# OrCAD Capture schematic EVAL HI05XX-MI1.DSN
size A; title: EVAL HI05XX-MI1; rev: A0; note: 1
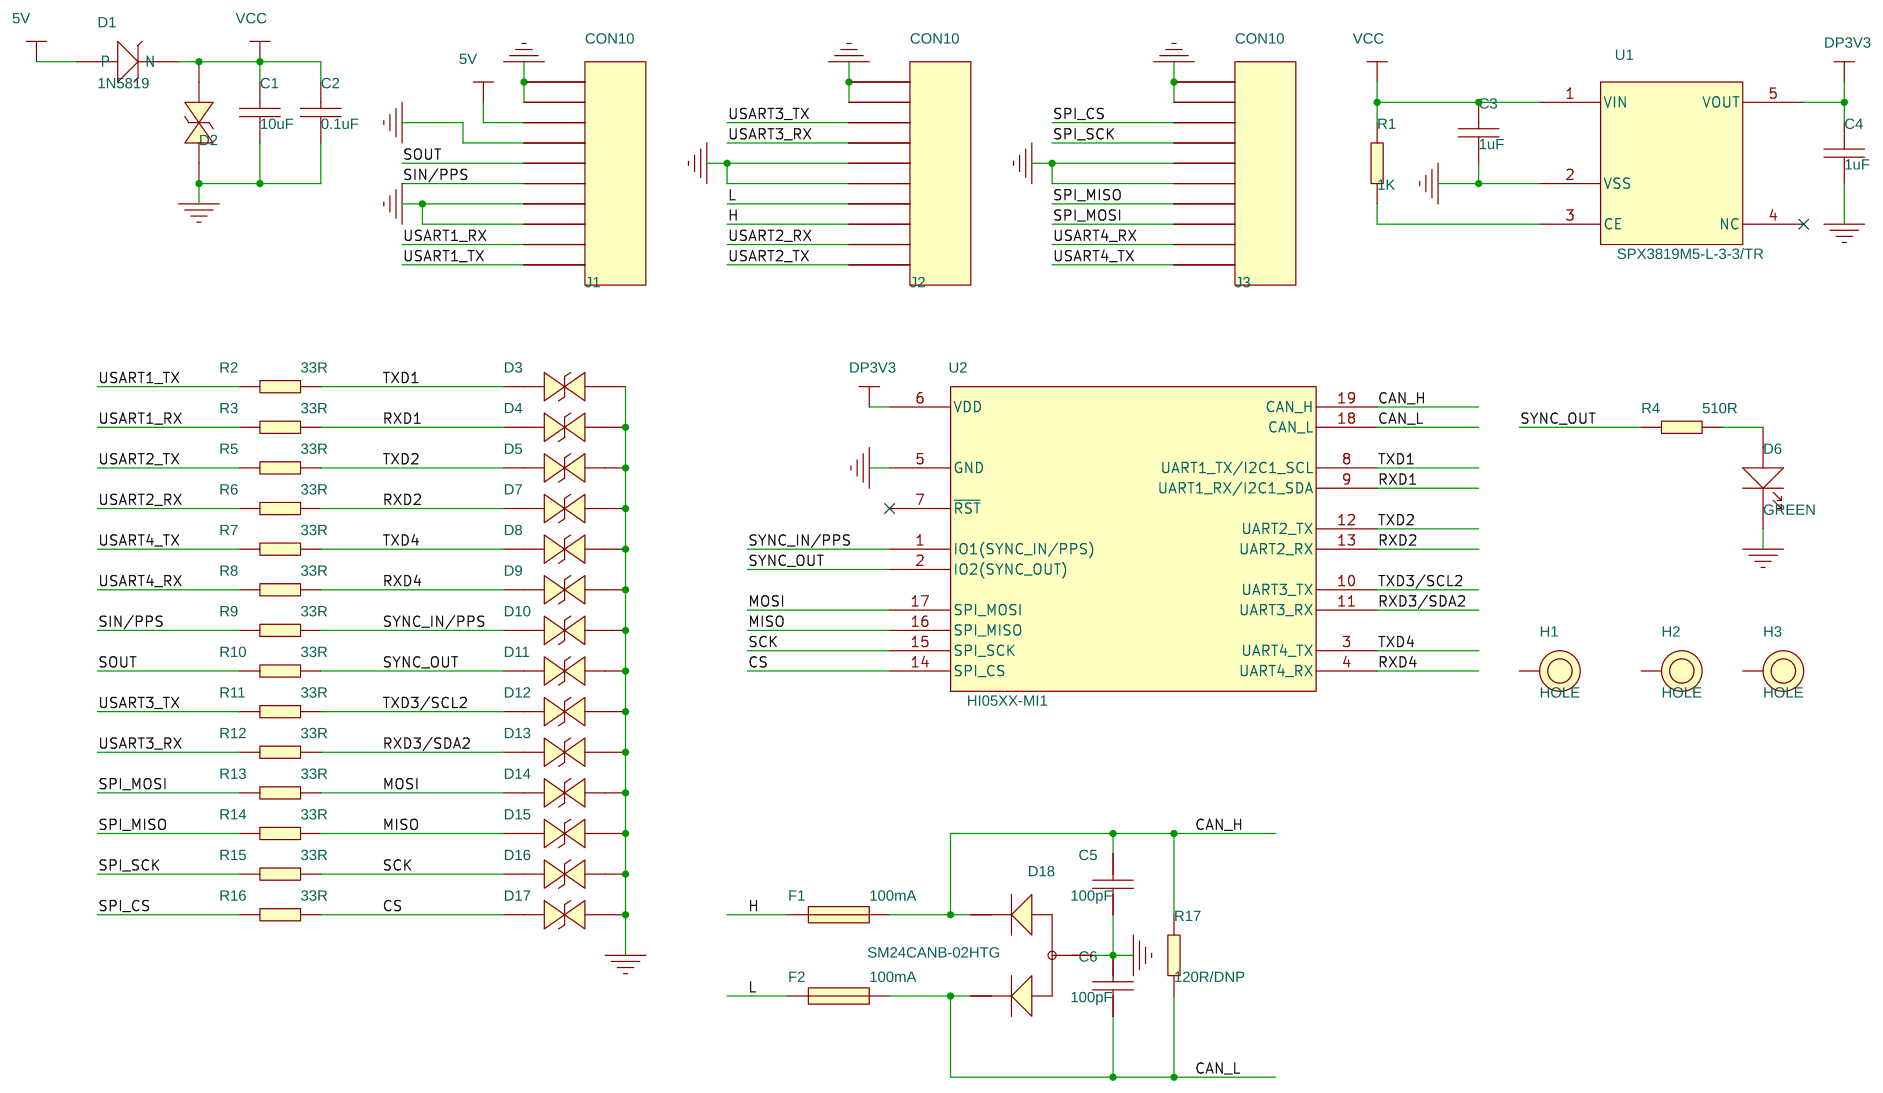
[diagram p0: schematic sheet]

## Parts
C1  10uF  [C0603]
C2  0.1uF  [C0402]
C3  1uF  [C0402]
C4  1uF  [C0402]
C5  100pF  [C0402]
C6  100pF  [C0402]
D1  1N5819  [SOD123FL]
D2  SDD32A05L01  [SOD123FL]
D3  SBD52C05L01  [SOD-523]
D4  SBD52C05L01  [SOD-523]
D5  SBD52C05L01  [SOD-523]
D6  GREEN  [LED0402]
D7  SBD52C05L01  [SOD-523]
D8  SBD52C05L01  [SOD-523]
D9  SBD52C05L01  [SOD-523]
D10  SBD52C05L01  [SOD-523]
D11  SBD52C05L01  [SOD-523]
D12  SBD52C05L01  [SOD-523]
D13  SBD52C05L01  [SOD-523]
D14  SBD52C05L01  [SOD-523]
D15  SBD52C05L01  [SOD-523]
D16  SBD52C05L01  [SOD-523]
D17  SBD52C05L01  [SOD-523]
D18  SM24CANB-02HTG  [SOT23-3-0_95]
F1  100mA  [F0603]
F2  100mA  [F0603]
H1  HOLE  [HOLE-2-MM]
H2  HOLE  [HOLE-2-MM]
H3  HOLE  [HOLE-2-MM]
J1  CON10  [5015680807_1]
J2  CON10  [5015680807_1]
J3  CON10  [5015680807_1]
R1  1K  [R0402]
R2  33R  [R0402]
R3  33R  [R0402]
R4  510R  [R0402]
R5  33R  [R0402]
R6  33R  [R0402]
R7  33R  [R0402]
R8  33R  [R0402]
R9  33R  [R0402]
R10  33R  [R0402]
R11  33R  [R0402]
R12  33R  [R0402]
R13  33R  [R0402]
R14  33R  [R0402]
R15  33R  [R0402]
R16  33R  [R0402]
R17  120R/DNP  [R0805]
U1  SPX3819M5-L-3-3/TR  [SOT23-5-0_95]
U2  HI05XX-MI1  [HI02_HI05]

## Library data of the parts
C1-C6 = Capacity_Nonpolarity
D1 = diode
D2-D5 D7-D17 = DIODE_BI-DIR_TRIG
D6 = LED
D18 = BAT54A_SOT
F1 F2 = Fuse
H1-H3 = HOLE
J1-J3 = CON10
R1-R17 = Res
U1 = XC6210
U2 = HI05XX-MI1

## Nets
5V: D1.1(P) J1.8
GND: C1.1 C2.1 C3.2 C4.1 C5.2 C6.1 D2.1 D3.1 D4.1 D5.1 D6.2(-) D7.1 D8.1 D9.1 D10.1 D11.1 D12.1 D13.1 D14.1 D15.1 D16.1 D17.1 D18.3 J1.3 J1.4 J1.7 J1.9 J1.10 J2.5 J2.6 J2.9 J2.10 J3.5 J3.6 J3.9 J3.10 U1.2(VSS) U2.5(GND)
VCC: C1.2 C2.2 C3.1 D1.2(N) D2.2 R1.2 U1.1(VIN)
CAN_H: C5.1 D18.1 F1.2 R17.2 U2.19(CAN_H)
CAN_L: C6.2 D18.2 F2.2 R17.1 U2.18(CAN_L)
CS: D17.2 R16.1 U2.14(SPI_CS)
DP3V3: C4.2 U1.5(VOUT) U2.6(VDD)
H: F1.1 J2.3
L: F2.1 J2.4
MISO: D15.2 R14.1 U2.16(SPI_MISO)
MOSI: D14.2 R13.1 U2.17(SPI_MOSI)
RXD1: D4.2 R3.1 U2.9(UART1_RX/I2C1_SDA)
RXD2: D7.2 R6.1 U2.13(UART2_RX)
RXD3/SDA2: D13.2 R12.1 U2.11(UART3_RX)
RXD4: D9.2 R8.1 U2.4(UART4_RX)
SCK: D16.2 R15.1 U2.15(SPI_SCK)
SIN/PPS: J1.5 R9.2
SOUT: J1.6 R10.2
SPI_CS: J3.8 R16.2
SPI_MISO: J3.4 R14.2
SPI_MOSI: J3.3 R13.2
SPI_SCK: J3.7 R15.2
SYNC_IN/PPS: D10.2 R9.1 U2.1(IO1(SYNC_IN/PPS))
SYNC_OUT: D11.2 R4.1 R10.1 U2.2(IO2(SYNC_OUT))
TXD1: D3.2 R2.1 U2.8(UART1_TX/I2C1_SCL)
TXD2: D5.2 R5.1 U2.12(UART2_TX)
TXD3/SCL2: D12.2 R11.1 U2.10(UART3_TX)
TXD4: D8.2 R7.1 U2.3(UART4_TX)
USART1_RX: J1.2 R3.2
USART1_TX: J1.1 R2.2
USART2_RX: J2.2 R6.2
USART2_TX: J2.1 R5.2
USART3_RX: J2.7 R12.2
USART3_TX: J2.8 R11.2
USART4_RX: J3.2 R8.2
USART4_TX: J3.1 R7.2
N2198535: D6.1(+) R4.2
N2224750: R1.1 U1.3(CE)

Not connected (* = marked no-connect by the designer): H1 1; H2 1; H3 1; U1 4(NC)*; U2 7(~{RST})*
